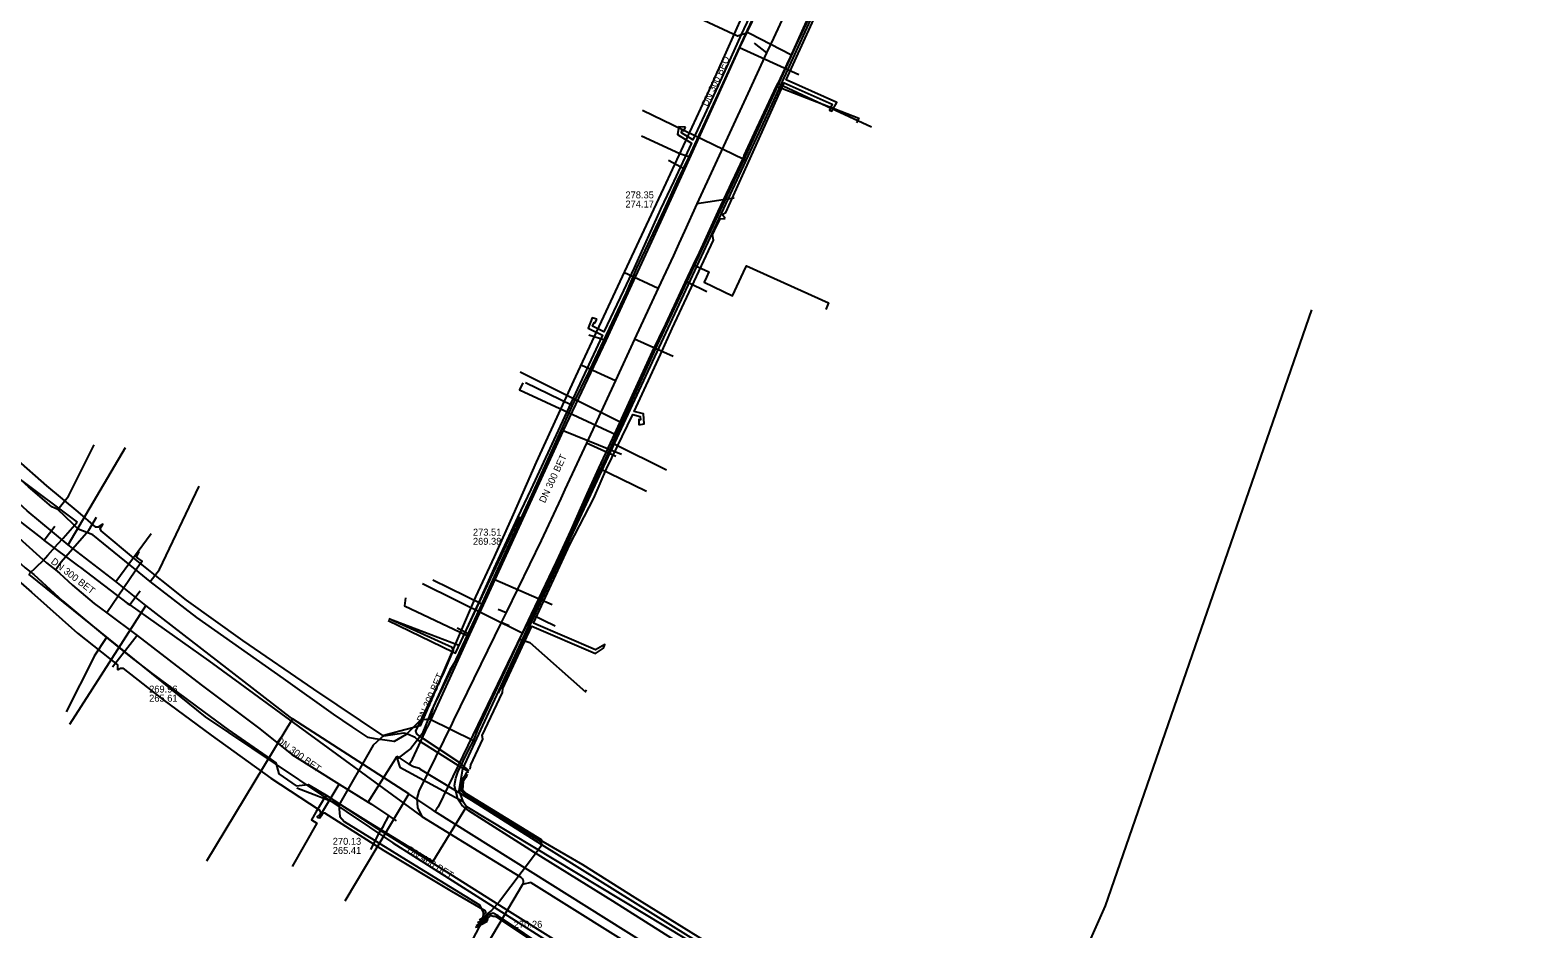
# Model space of a CAD drawing. Extents: x -600309 to -598967, y -1161267 to -1160292.
# Drawn here: x -600169 to -599995.5, y -1160530.2 to -1160426.8 of the extents above; entities that cross this region are included whole.
import ezdxf

# ---------------------------------------------------------------- set-up
doc = ezdxf.new("R2010")
doc.units = 0
for name, color, linetype in [('Vrstva 12', 7, 'Continuous'), ('Vrstva 13', 7, 'Continuous'), ('Vrstva 19', 7, 'Continuous'), ('Vrstva 42', 7, 'Continuous'), ('Vrstva 54', 7, 'Continuous'), ('Vrstva 55', 7, 'Continuous'), ('Vrstva 58', 7, 'Continuous'), ('Vrstva 9', 7, 'Continuous')]:
    doc.layers.add(name, color=color, linetype=linetype)

msp = doc.modelspace()

# ---------------------------------------------------------------- linework, layer by layer
at = {"layer": 'Vrstva 12'}
for points in [[(-600081.32, -1160415.78), (-600086.7, -1160427.39), (-600089.44, -1160433.33), (-600093.17, -1160441.4)], [(-600083.05, -1160433.26), (-600082.47, -1160432.14), (-600078.78, -1160423.93)], [(-600092.6, -1160453.82), (-600091.13, -1160450.75), (-600088.1, -1160444.08), (-600087.09, -1160442.06), (-600086.68, -1160441.75), (-600086.78, -1160441.23), (-600085.61, -1160438.68), (-600083.05, -1160433.26)], [(-600083.05, -1160433.26), (-600073.6, -1160436.93), (-600073.85, -1160437.47)], [(-600093.17, -1160441.4), (-600094.18, -1160441.06), (-600098.61, -1160439)], [(-600093.17, -1160441.4), (-600094.52, -1160444.21), (-600096.03, -1160447.54), (-600099.19, -1160454.22), (-600100.38, -1160457.01), (-600104.61, -1160466.02), (-600106.57, -1160470)], [(-600103.53, -1160477.21), (-600101.89, -1160473.78), (-600099.02, -1160467.46), (-600097.33, -1160463.8), (-600095.82, -1160460.65), (-600093.57, -1160455.86), (-600092.6, -1160453.82)], [(-600092.6, -1160453.82), (-600090.85, -1160454.62), (-600091.14, -1160455.24)], [(-600091.14, -1160455.24), (-600091.4, -1160455.82), (-600088.13, -1160457.4), (-600086.86, -1160454.67), (-600086.53, -1160453.95), (-600077.07, -1160458.2), (-600077.4, -1160458.94)], [(-600057.6, -1160554.69), (-600056.27, -1160552.44), (-600045.21, -1160527.6), (-600021.46, -1160458.99)], [(-600106.57, -1160470), (-600111.94, -1160467.39)], [(-600165.76, -1160481.99), (-600166.47, -1160481.68), (-600169.14, -1160479.36), (-600171.58, -1160477.13), (-600174.19, -1160474.62), (-600178.16, -1160470.54)], [(-600106.57, -1160470), (-600111.07, -1160479.92), (-600112.51, -1160483.1), (-600115.18, -1160488.83), (-600116.9, -1160492.66), (-600116.98, -1160492.83)], [(-600165.76, -1160481.99), (-600164.53, -1160480.43), (-600161.59, -1160474.52)], [(-600112.61, -1160496.92), (-600110.61, -1160492.83), (-600106.72, -1160484.43), (-600104.86, -1160480.16), (-600103.53, -1160477.21)], [(-600103.53, -1160477.21), (-600102.36, -1160477.76), (-600098.04, -1160479.85)], [(-600155.13, -1160490.25), (-600154.05, -1160488.87), (-600149.5, -1160479.29)], [(-600177.97, -1160480.86), (-600172.74, -1160485.78), (-600169.52, -1160488.7), (-600168.51, -1160489.47), (-600165.23, -1160492.5), (-600160.18, -1160496.71)], [(-600155.13, -1160490.25), (-600156.84, -1160488.89), (-600161.73, -1160484.9), (-600163.43, -1160484.26), (-600164.04, -1160483.63), (-600165.76, -1160481.99)], [(-600131.91, -1160506.99), (-600134.06, -1160505.54), (-600139.78, -1160501.43), (-600149.76, -1160494.41), (-600155.13, -1160490.25)], [(-600122.61, -1160490.07), (-600116.98, -1160492.83)], [(-600116.98, -1160492.83), (-600119.49, -1160498.26), (-600120.04, -1160499.49), (-600120.66, -1160500.48), (-600122.55, -1160504.62), (-600123.01, -1160506.12)], [(-600160.18, -1160496.71), (-600161.57, -1160498.85), (-600161.63, -1160498.97)], [(-600160.18, -1160496.71), (-600157.36, -1160498.96), (-600155.02, -1160500.77), (-600148.95, -1160505.27), (-600146.22, -1160507.29), (-600141.2, -1160510.75), (-600140.69, -1160511.15), (-600140.32, -1160512.41), (-600138.33, -1160513.8), (-600136.97, -1160513.64), (-600134.87, -1160514.87)], [(-600117.94, -1160508.61), (-600117.37, -1160507.16), (-600114.34, -1160500.66), (-600112.61, -1160496.92)], [(-600112.61, -1160496.92), (-600111.46, -1160497.3), (-600105.03, -1160502.95), (-600104.92, -1160502.72)], [(-600161.63, -1160498.97), (-600164.79, -1160505.25)], [(-600129.24, -1160508.36), (-600130.04, -1160508.24), (-600131.91, -1160506.99)], [(-600123.01, -1160506.12), (-600124.02, -1160506.22), (-600125.69, -1160507.88), (-600127.07, -1160508.68), (-600128.4, -1160508.48)], [(-600117.94, -1160508.61), (-600123.01, -1160506.12)], [(-600128.4, -1160508.48), (-600129.24, -1160508.36)], [(-600070.97, -1160546.36), (-600072.28, -1160545.55), (-600074, -1160544.59), (-600076.31, -1160543.2), (-600076.76, -1160542.71), (-600080.09, -1160540.63), (-600081.1, -1160539.99), (-600083.42, -1160538.6), (-600083.85, -1160538.51), (-600101.91, -1160527.04), (-600110.99, -1160521.4), (-600118.48, -1160516.68), (-600119.28, -1160516.02), (-600119.74, -1160515.31), (-600120.13, -1160513.75), (-600119.98, -1160512.91), (-600119.73, -1160512.22), (-600118.51, -1160509.69), (-600117.94, -1160508.61)], [(-600134.87, -1160514.87), (-600136.09, -1160516.83), (-600136.59, -1160517.71), (-600135.96, -1160518.1), (-600138.81, -1160523.08)], [(-600134.87, -1160514.87), (-600129.05, -1160518.66), (-600122.85, -1160522.53), (-600113.48, -1160528.44), (-600101.18, -1160536.15)]]:
    msp.add_lwpolyline(points, dxfattribs=at)
at = {"layer": 'Vrstva 13'}
for p, q in [((-600086.84, -1160441.71), (-600098.48, -1160436.04)), ((-600100.83, -1160472.03), (-600112.55, -1160466.16)), ((-600164.57, -1160486.03), (-600157.99, -1160474.83)), ((-600159.08, -1160490.28), (-600155.04, -1160484.74)), ((-600112.35, -1160496.21), (-600123.79, -1160490.54)), ((-600155.63, -1160493.03), (-600164.43, -1160506.72)), ((-600111.31, -1160494.03), (-600108.53, -1160495.36)), ((-600138.76, -1160506.07), (-600148.66, -1160522.45)), ((-600125.36, -1160514.72), (-600132.73, -1160527.06)), ((-600122.37, -1160516.74), (-600122.7, -1160516.51)), ((-600122.37, -1160516.74), (-600122.19, -1160516.47))]:
    msp.add_line(p, q, dxfattribs=at)
for points in [[(-600043.34, -1160353.45), (-600045.14, -1160355.65), (-600059.5, -1160382.79), (-600064.92, -1160394.07), (-600067.21, -1160399.06), (-600067.79, -1160400.26), (-600068.48, -1160401.76), (-600074.11, -1160413.88), (-600075.99, -1160417.88), (-600082.54, -1160432.28), (-600086.84, -1160441.71), (-600093.4, -1160455.74), (-600098.87, -1160467.43), (-600100.83, -1160472.03), (-600101.9, -1160474.35), (-600111.31, -1160494.03), (-600112.35, -1160496.21), (-600121.99, -1160516.19), (-600122.19, -1160516.47)], [(-600081.34, -1160429.68), (-600080.15, -1160427.2), (-600071.2, -1160407.88), (-600062.68, -1160389.74), (-600049.97, -1160365.66)], [(-600122.7, -1160516.51), (-600125.36, -1160514.72), (-600138.76, -1160506.07), (-600139.03, -1160505.89), (-600155.63, -1160493.03), (-600159.08, -1160490.28), (-600164.57, -1160486.03), (-600169.31, -1160482.14), (-600178.89, -1160473.39), (-600189.51, -1160463.15), (-600195.69, -1160457.44), (-600198.6, -1160454.7), (-600199.2, -1160454.12), (-600201.09, -1160452.35), (-600215.37, -1160438.87), (-600221.37, -1160432.92), (-600233.85, -1160421.19)], [(-600081.34, -1160429.68), (-600086.18, -1160427.21), (-600086.38, -1160427.11), (-600087.54, -1160427.5), (-600091.94, -1160425.46), (-600091.8, -1160425.15)], [(-600082.87, -1160432.96), (-600081.84, -1160430.72)], [(-600081.84, -1160430.72), (-600081.34, -1160429.68)], [(-600083.66, -1160434.66), (-600082.87, -1160432.96)], [(-600082.87, -1160432.96), (-600077.26, -1160435.55)], [(-600101.22, -1160472.82), (-600089.77, -1160447.68), (-600083.66, -1160434.66)], [(-600077.26, -1160435.55), (-600072.12, -1160437.94)], [(-600093.4, -1160455.74), (-600093.18, -1160455.85), (-600091.08, -1160456.9)], [(-600112.26, -1160467.41), (-600112.64, -1160468.21), (-600106.49, -1160471.05), (-600101.46, -1160473.37)], [(-600102.22, -1160475.02), (-600101.65, -1160473.78)], [(-600101.65, -1160473.78), (-600101.46, -1160473.37)], [(-600101.46, -1160473.37), (-600101.22, -1160472.82)], [(-600119.11, -1160515.59), (-600119.6, -1160514.32), (-600119.18, -1160511.84), (-600112.5, -1160497.37), (-600102.22, -1160475.02)], [(-600101.9, -1160474.35), (-600101.67, -1160474.45), (-600095.74, -1160477.42)], [(-600125.77, -1160492.16), (-600125.89, -1160493.05), (-600119.47, -1160496.1)], [(-600119.47, -1160496.1), (-600118.66, -1160496.48), (-600120.63, -1160500.64)], [(-600120.63, -1160500.64), (-600122.76, -1160505.11), (-600123.35, -1160506.58)], [(-600123.35, -1160506.58), (-600123.84, -1160507.79), (-600125.16, -1160509.48), (-600126.73, -1160510.69), (-600126.41, -1160511.64), (-600119.11, -1160515.59)], [(-600133.09, -1160516.06), (-600138.27, -1160514.04)], [(-600119.11, -1160515.59), (-600118.73, -1160516.18)], [(-600118.73, -1160516.18), (-600122.6, -1160522.51), (-600130.03, -1160517.96), (-600133.09, -1160516.06)], [(-599975.85, -1160601.96), (-599976.16, -1160601.85), (-599999.47, -1160590.82), (-600019.43, -1160580.36), (-600019.59, -1160580.27), (-600041.8, -1160567.42), (-600043.37, -1160566.46), (-600058.27, -1160556.95), (-600068.65, -1160550.45), (-600070.85, -1160549.1), (-600072.45, -1160548.13), (-600077.78, -1160544.7), (-600080.37, -1160543.08), (-600085.86, -1160539.73), (-600091.61, -1160536.05), (-600122.37, -1160516.74)], [(-600118.73, -1160516.18), (-600093.42, -1160531.44)]]:
    msp.add_lwpolyline(points, dxfattribs=at)
at = {"layer": 'Vrstva 19'}
for points in [[(-600051.43, -1160357), (-600051.67, -1160357.47), (-600052.24, -1160358.5), (-600053.88, -1160361.41), (-600054.44, -1160362.42), (-600057.61, -1160367.59), (-600060.27, -1160372.46), (-600066.42, -1160384.21), (-600071.99, -1160395.91), (-600072.44, -1160396.86), (-600081.21, -1160416.01), (-600081.68, -1160417.02), (-600087.34, -1160428.81), (-600093.67, -1160442.82), (-600097.21, -1160450.62), (-600102.72, -1160462.51), (-600107.62, -1160472.9), (-600115.47, -1160490.04), (-600118.4, -1160496.38), (-600123.24, -1160507.01)], [(-600087.34, -1160428.81), (-600080.51, -1160431.91)], [(-600093.67, -1160442.82), (-600095.49, -1160441.82)], [(-600102.72, -1160462.51), (-600104.68, -1160461.93)], [(-600107.62, -1160472.9), (-600100.9, -1160475.61)], [(-600176.22, -1160479.86), (-600167.06, -1160488.13), (-600166.04, -1160488.94), (-600165.59, -1160489.32), (-600164.08, -1160490.67), (-600161.58, -1160492.79), (-600160.11, -1160493.89), (-600156.65, -1160496.5), (-600149.27, -1160502.17), (-600142.52, -1160507.24), (-600138.85, -1160510.19), (-600133.38, -1160513.59), (-600130.04, -1160515.65), (-600129.69, -1160515.89)], [(-600166.04, -1160488.94), (-600165.39, -1160488.02), (-600162.18, -1160484.35), (-600161.32, -1160482.86)], [(-600156.2, -1160488.1), (-600160.11, -1160493.89)], [(-600156.2, -1160488.1), (-600156.07, -1160487.92), (-600156.71, -1160487.46), (-600156.39, -1160486.83)], [(-600115.47, -1160490.04), (-600108.87, -1160492.93)], [(-600156.65, -1160496.5), (-600159.47, -1160500.12)], [(-600118.4, -1160496.38), (-600119.82, -1160495.62)], [(-600125.32, -1160511.28), (-600124.97, -1160510.7), (-600123.24, -1160507.01)], [(-600130.04, -1160515.65), (-600126.7, -1160510.37)], [(-600125.32, -1160511.28), (-600126.7, -1160510.37)], [(-600125.32, -1160511.28), (-600124.82, -1160511.55), (-600124.15, -1160511.76), (-600124.03, -1160511.9)], [(-600015.21, -1160579.25), (-600017.76, -1160577.91), (-600017.95, -1160577.81), (-600024.7, -1160574.09), (-600035.34, -1160567.49), (-600040.58, -1160564.31), (-600055.41, -1160554.78), (-600068.22, -1160546.87), (-600074.61, -1160542.73), (-600082.12, -1160538.04), (-600082.55, -1160537.77), (-600083.33, -1160537.27), (-600089.82, -1160533.16), (-600093.19, -1160531.07), (-600110.07, -1160520.59), (-600118.12, -1160515.46), (-600124.03, -1160511.9)], [(-600135.66, -1160517.37), (-600133.38, -1160513.59)], [(-600129.69, -1160515.89), (-600127.66, -1160517.25), (-600126.82, -1160517.81)], [(-600128.34, -1160518.47), (-600127.66, -1160517.25)], [(-600128.82, -1160519.25), (-600129.8, -1160521.11)], [(-600128.34, -1160518.47), (-600128.82, -1160519.25)]]:
    msp.add_lwpolyline(points, dxfattribs=at)
at = {"layer": 'Vrstva 42'}
for points in [[(-600088.96, -1160448.5), (-600089.32, -1160448.04), (-600088.9, -1160447.78), (-600085.42, -1160440.03), (-600082.17, -1160432.87), (-600076.67, -1160435.34), (-600076.98, -1160436.02), (-600076.71, -1160436.14), (-600076.14, -1160435.14), (-600081.96, -1160432.53), (-600077.96, -1160423.79), (-600076.54, -1160420.8), (-600074.55, -1160416.28), (-600069.56, -1160418.65), (-600069.53, -1160418.58), (-600074.5, -1160416.13), (-600071.26, -1160409.31), (-600070.05, -1160406.52), (-600066.08, -1160398.2), (-600064.59, -1160398.78), (-600064.74, -1160399.06), (-600065.15, -1160398.93), (-600065.32, -1160399.45)], [(-600082.3, -1160415.3), (-600081.61, -1160415.57), (-600087.15, -1160427.32), (-600088.34, -1160429.95), (-600088.63, -1160430.63), (-600089.79, -1160433.16), (-600092.7, -1160439.43), (-600094.01, -1160438.61), (-600093.97, -1160438.35), (-600093.72, -1160438.38), (-600093.52, -1160437.96)], [(-600093.52, -1160437.96), (-600094.32, -1160437.92), (-600094.44, -1160438.81), (-600092.86, -1160439.8), (-600094.88, -1160444.17), (-600096.4, -1160447.4), (-600099.45, -1160454.17), (-600100.66, -1160456.76), (-600102.92, -1160461.53), (-600104.23, -1160460.89), (-600104.05, -1160460.46), (-600103.95, -1160460.51), (-600103.74, -1160460.06)], [(-600098.89, -1160472.25), (-600098.28, -1160472.12), (-600098.37, -1160470.98), (-600099.45, -1160470.68), (-600096.43, -1160464.13), (-600095.06, -1160461.13), (-600090.31, -1160450.97), (-600090.44, -1160450.37), (-600090.22, -1160449.86)], [(-600090.22, -1160449.86), (-600089.56, -1160448.53), (-600088.96, -1160448.5)], [(-600103.74, -1160460.06), (-600104.27, -1160459.93), (-600104.74, -1160461.09), (-600103.08, -1160461.9), (-600106.73, -1160469.73), (-600111.33, -1160479.69), (-600112.86, -1160482.88), (-600115.58, -1160488.77), (-600117.16, -1160492.3), (-600119.61, -1160497.65), (-600127.67, -1160494.57)], [(-600118.3, -1160511.88), (-600118.24, -1160511.38), (-600116.85, -1160508.43), (-600116.95, -1160507.98), (-600114.61, -1160503.03), (-600114.54, -1160502.6), (-600112.35, -1160497.78), (-600111.22, -1160495.42), (-600103.89, -1160498.57), (-600102.98, -1160497.92), (-600102.81, -1160497.53), (-600103.91, -1160498.13), (-600111.04, -1160495.06), (-600106.83, -1160486), (-600104.1, -1160480.66), (-600102.64, -1160477.3), (-600099.59, -1160471.05), (-600098.75, -1160471.29), (-600098.72, -1160471.64), (-600098.91, -1160471.61), (-600098.89, -1160472.25)], [(-600118.5, -1160512.13), (-600118.96, -1160511.87), (-600119.71, -1160511.44), (-600124.36, -1160508.48), (-600124.65, -1160508.23), (-600125.52, -1160507.83), (-600125.94, -1160507.73), (-600128.26, -1160508.07), (-600136.31, -1160502.65), (-600144.48, -1160497.05), (-600150.95, -1160492.43), (-600156.81, -1160487.74), (-600160.78, -1160484.43), (-600160.89, -1160484.15), (-600160.57, -1160483.65), (-600161.14, -1160484), (-600161.39, -1160484), (-600163.41, -1160482.24), (-600167.04, -1160479.25), (-600170.59, -1160476.11)], [(-600127.76, -1160494.75), (-600120.31, -1160498.36), (-600120.01, -1160498.51), (-600112.62, -1160482.77)], [(-600178.54, -1160483.59), (-600178.2, -1160483.37), (-600177.89, -1160483.4), (-600173.97, -1160487), (-600168.81, -1160491.51), (-600163.52, -1160496.2), (-600158.91, -1160499.84), (-600158.91, -1160500.43)], [(-600118.44, -1160512.07), (-600119.52, -1160511.13), (-600124.15, -1160508.07), (-600124.47, -1160507.8), (-600124.56, -1160507.51), (-600123.83, -1160505.95), (-600121.32, -1160500.7), (-600120.31, -1160498.36), (-600120.24, -1160498.19), (-600120.4, -1160497.87), (-600127.67, -1160494.57)], [(-600158.91, -1160500.43), (-600158.57, -1160500.23), (-600158.3, -1160500.25), (-600153.68, -1160503.86), (-600148.13, -1160507.96), (-600141.24, -1160512.9), (-600135.7, -1160516.53), (-600135.5, -1160516.91), (-600135.52, -1160516.96), (-600135.72, -1160517.25), (-600135.79, -1160517.23), (-600135.91, -1160517.31), (-600135.86, -1160517.42), (-600135.62, -1160517.47), (-600135.36, -1160517.08), (-600135.31, -1160516.98), (-600135.07, -1160516.9), (-600128.27, -1160521.23), (-600120.46, -1160525.92), (-600116.62, -1160528.14), (-600116.51, -1160528.37), (-600116.81, -1160528.66), (-600116.9, -1160529.03), (-600117.3, -1160529.26)], [(-600118.5, -1160512.22), (-600118.79, -1160512.3), (-600119.01, -1160512.73), (-600119.31, -1160513.22), (-600119.41, -1160514.33), (-600118.91, -1160514.82), (-600110.24, -1160520.16), (-600110.09, -1160520.48), (-600110.23, -1160520.8), (-600111.04, -1160521.92), (-600114.93, -1160527.11), (-600115.86, -1160528.15), (-600116.35, -1160528.5), (-600116.63, -1160528.77), (-600116.73, -1160529.17), (-600117.46, -1160529.57)], [(-600118.65, -1160512.45), (-600118.83, -1160512.83), (-600119.11, -1160513.28), (-600119.21, -1160514.25), (-600118.79, -1160514.66), (-600110.14, -1160519.98), (-600109.95, -1160520.21), (-600105.39, -1160522.82), (-600099.35, -1160526.63), (-600091.33, -1160531.63)], [(-600095.74, -1160545.07), (-600095.74, -1160544.88), (-600094.45, -1160542.66), (-600094.38, -1160542.46), (-600094.4, -1160542.29), (-600094.47, -1160542.19), (-600095.39, -1160541.5), (-600097.95, -1160540.05), (-600102.65, -1160537.11), (-600109.02, -1160533.04), (-600115.23, -1160528.89), (-600115.48, -1160528.82), (-600115.68, -1160528.83), (-600116.01, -1160528.71), (-600116.07, -1160528.78), (-600116.27, -1160528.97), (-600116.39, -1160529.43), (-600117.54, -1160530.07), (-600117.76, -1160530.08)], [(-600079.95, -1160553.1), (-600079.82, -1160552.99), (-600079.48, -1160552.73), (-600079.07, -1160552.05), (-600079.01, -1160551.5), (-600079.29, -1160551.18), (-600085.53, -1160547.42), (-600089.96, -1160544.74), (-600093.79, -1160542.47), (-600094.11, -1160542.25), (-600094.35, -1160542.03), (-600095.29, -1160541.34), (-600097.85, -1160539.87), (-600102.55, -1160536.95), (-600108.92, -1160532.88), (-600115.11, -1160528.73), (-600115.66, -1160528.43), (-600116.21, -1160528.64), (-600116.45, -1160528.87), (-600116.56, -1160529.3), (-600117.64, -1160529.9)]]:
    msp.add_lwpolyline(points, dxfattribs=at)
at = {"layer": 'Vrstva 54'}
for points in [[(-600204.17, -1160445.46), (-600184.16, -1160468.02), (-600163.56, -1160483.42)], [(-600169.04, -1160489.34), (-600167.46, -1160487.83), (-600166.91, -1160487.24), (-600165.77, -1160485.94), (-600165.17, -1160485.29), (-600163.56, -1160483.42)]]:
    msp.add_lwpolyline(points, dxfattribs=at)
at = {"layer": 'Vrstva 55'}
for points in [[(-600052.28, -1160370.18), (-600052.64, -1160370.62), (-600062.46, -1160389.3), (-600070.54, -1160406.63), (-600084.85, -1160438), (-600100.93, -1160472.64), (-600115.08, -1160503.1)], [(-600169.13, -1160489.44), (-600148.81, -1160505.86), (-600127.23, -1160520.33), (-600105.48, -1160534.14), (-600101.57, -1160536.29), (-600083.32, -1160547.71), (-600061.3, -1160561.63), (-600039.15, -1160575.32), (-600016.63, -1160588.31), (-600008.17, -1160593.08), (-599993.4, -1160599.75)]]:
    msp.add_lwpolyline(points, dxfattribs=at)
at = {"layer": 'Vrstva 58'}
for points in [[(-600086.97, -1160425.09), (-600090.81, -1160433.66), (-600095.8, -1160444.4), (-600100.04, -1160453.45), (-600106.19, -1160466.66), (-600110.72, -1160476.53), (-600113.37, -1160482.55), (-600115.57, -1160487.43), (-600117.71, -1160492.03), (-600124.09, -1160506.86), (-600126.4, -1160507.5)], [(-600126.4, -1160507.5), (-600128.24, -1160507.99), (-600129.48, -1160509.09), (-600133.44, -1160516.01), (-600133.33, -1160517.33), (-600132.82, -1160517.89), (-600125.19, -1160522.6), (-600117.25, -1160527.47), (-600116.82, -1160528.38), (-600116.85, -1160529.22), (-600118.07, -1160531.54)]]:
    msp.add_lwpolyline(points, dxfattribs=at)
at = {"layer": 'Vrstva 9'}
for p, q in [((-600085.62, -1160428.31), (-600084.2, -1160429.43)), ((-600087.92, -1160446.14), (-600092.25, -1160446.81)), ((-600100.63, -1160454.68), (-600096.68, -1160456.5)), ((-600094.95, -1160464.36), (-600099.4, -1160462.38)), ((-600105.45, -1160465.35), (-600101.6, -1160467.13)), ((-600101.54, -1160475.89), (-600104.93, -1160474.33)), ((-600166.11, -1160483.93), (-600167.32, -1160485.53)), ((-600156.3, -1160491.36), (-600157.5, -1160492.95)), ((-600115.11, -1160493.46), (-600114.19, -1160493.85)), ((-600113.83, -1160495.38), (-600114.74, -1160494.98))]:
    msp.add_line(p, q, dxfattribs=at)
for points in [[(-600076.84, -1160413.6), (-600078.57, -1160417.22), (-600078.73, -1160417.56), (-600078.97, -1160418.09), (-600083.41, -1160427.73)], [(-600083.41, -1160427.73), (-600084.2, -1160429.43), (-600086.35, -1160434.08)], [(-600086.35, -1160434.08), (-600092.25, -1160446.81), (-600093.64, -1160449.93)], [(-600093.64, -1160449.93), (-600094.29, -1160451.35), (-600094.93, -1160452.73), (-600096.68, -1160456.5), (-600099.4, -1160462.38), (-600101.6, -1160467.13), (-600104.93, -1160474.33), (-600107.41, -1160479.67), (-600107.88, -1160480.7), (-600110.13, -1160485.55)], [(-600172.49, -1160481.55), (-600167.66, -1160485.27), (-600167.32, -1160485.53), (-600163.39, -1160488.51), (-600163.17, -1160488.67), (-600157.78, -1160492.76), (-600157.5, -1160492.95), (-600148.4, -1160499.39)], [(-600110.13, -1160485.55), (-600114.19, -1160493.85), (-600114.74, -1160494.98), (-600120.25, -1160506.23), (-600120.4, -1160506.56), (-600124.23, -1160514.39), (-600124.46, -1160515.24), (-600124.36, -1160516.26), (-600123.88, -1160517.3)], [(-600148.4, -1160499.39), (-600139.09, -1160506.19), (-600123.88, -1160517.3)], [(-600123.88, -1160517.3), (-600116.82, -1160521.65), (-600112.49, -1160524.29), (-600112.45, -1160524.32), (-600112.4, -1160524.36), (-600112.36, -1160524.4), (-600112.32, -1160524.46), (-600112.28, -1160524.52), (-600112.26, -1160524.56), (-600112.25, -1160524.59), (-600112.24, -1160524.64), (-600112.23, -1160524.68), (-600112.22, -1160524.73), (-600112.22, -1160524.78), (-600112.22, -1160524.83), (-600112.22, -1160524.88), (-600112.23, -1160524.93), (-600112.24, -1160524.99), (-600112.26, -1160525.03), (-600112.28, -1160525.08), (-600112.3, -1160525.11), (-600112.31, -1160525.13)], [(-600112.31, -1160525.13), (-600119.1, -1160536.6), (-600121.04, -1160539.89), (-600123.93, -1160544.76)], [(-600078.3, -1160545.61), (-600078.89, -1160545.24), (-600111.31, -1160524.93), (-600111.33, -1160524.92), (-600112.31, -1160525.13)]]:
    msp.add_lwpolyline(points, dxfattribs=at)

# ---------------------------------------------------------------- texts
at = {"layer": 'Vrstva 12'}
for s, rotation, p in [('DN 300 BEO', 65.2026, (-600091.01, -1160435.65)), ('DN 300 BET', 65.1299, (-600109.71, -1160481.3)), ('DN 300 BET', 322.4152, (-600166.64, -1160488.11)), ('DN 300 BET', 66.4132, (-600123.77, -1160506.54)), ('DN 300 BET', 323.8554, (-600140.7, -1160508.72)), ('DN 400 BET', 328.272, (-600125.66, -1160521.36))]:
    msp.add_text(s, height=0.8, rotation=rotation, dxfattribs=at).set_placement(p)
for s, p in [('278.35', (-600100.45, -1160446.17)), ('274.17', (-600100.45, -1160447.22)), ('273.51', (-600118, -1160484.99)), ('269.38', (-600118, -1160486.04)), ('269.96', (-600155.26, -1160503.05)), ('265.61', (-600155.26, -1160504.1)), ('270.13', (-600134.13, -1160520.57)), ('265.41', (-600134.13, -1160521.62)), ('270.26', (-600113.29, -1160530.12))]:
    msp.add_text(s, height=0.8, dxfattribs=at).set_placement(p)

doc.saveas('drawing.dxf')
